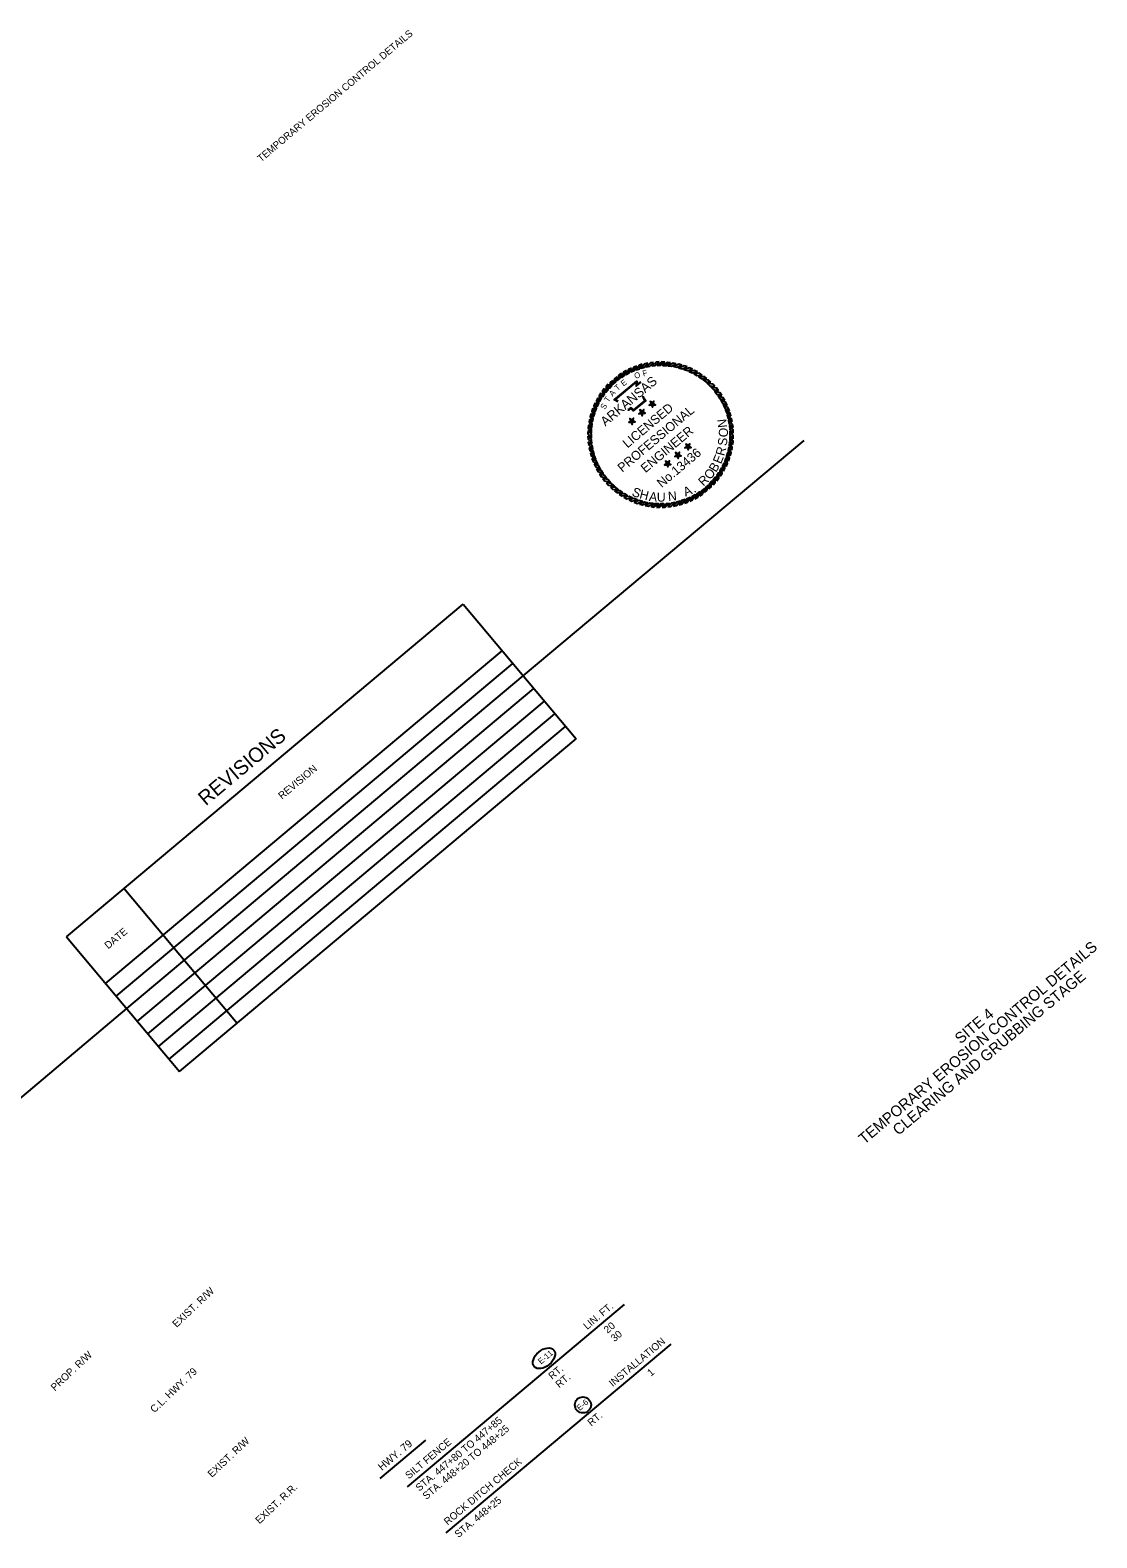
# Model space of a CAD drawing. Extents: x 1430270 to 1431940, y 1964864 to 1966264.
# Drawn here: x 1431064 to 1431940, y 1965025 to 1966264 of the extents above; entities that cross this region are included whole.
import ezdxf

# ---------------------------------------------------------------- set-up
doc = ezdxf.new("R2010")
doc.units = 0
for name, color, linetype in [('1', 7, 'Continuous'), ('44', 7, 'Continuous'), ('60', 7, 'Continuous'), ('Default', 7, 'Continuous'), ('G-ANNO-SYMB', 7, 'Continuous'), ('R_Draft', 7, 'Continuous')]:
    doc.layers.add(name, color=color, linetype=linetype)

msp = doc.modelspace()

# ---------------------------------------------------------------- linework, layer by layer
at = {"layer": '1'}
for p, q in [((1431469.3, 1965733.3), (1431699.9, 1965926.7)), ((1430924.6, 1965276.1), (1431143.8, 1965460.1))]:
    msp.add_line(p, q, dxfattribs=at)
msp.add_circle((1431518.4, 1965134.6), 6.61, dxfattribs=at)
msp.add_ellipse((1431486.4, 1965172.9), major_axis=(8.06, 6.76), ratio=0.638788, dxfattribs=at)
at = {"layer": '44'}
for p, q in [((1431374.3, 1965067.4), (1431552.6, 1965217.1)), ((1431406.1, 1965029.6), (1431590.7, 1965184.5)), ((1431352, 1965074.3), (1431389.4, 1965105.7))]:
    msp.add_line(p, q, dxfattribs=at)
at = {"layer": 'Default'}
for p, q in [((1431094.3, 1965519.1), (1431419.9, 1965792.3)), ((1431419.9, 1965792.3), (1431512.7, 1965681.6)), ((1431126.4, 1965480.8), (1431452, 1965754)), ((1431135.1, 1965470.4), (1431460.7, 1965743.6)), ((1431143.8, 1965460.1), (1431469.3, 1965733.3)), ((1431152.5, 1965449.7), (1431478, 1965722.9)), ((1431152.5, 1965449.7), (1431478, 1965722.9)), ((1431161.1, 1965439.4), (1431486.7, 1965712.6)), ((1431169.8, 1965429.1), (1431495.4, 1965702.2)), ((1431178.5, 1965418.7), (1431504.1, 1965691.9)), ((1431187.2, 1965408.4), (1431512.7, 1965681.6)), ((1431141.6, 1965558.8), (1431234.5, 1965448.1)), ((1431094.3, 1965519.1), (1431187.2, 1965408.4))]:
    msp.add_line(p, q, dxfattribs=at)
at = {"layer": 'G-ANNO-SYMB'}
for points in [[(1431567.1, 1965989.3), (1431564.7, 1965988.6), (1431562.1, 1965984.8), (1431564.7, 1965985.7)], [(1431571.7, 1965990.3), (1431569.2, 1965989.8), (1431566.3, 1965986.2), (1431569, 1965986.9)], [(1431576.3, 1965990.9), (1431573.8, 1965990.6), (1431570.6, 1965987.3), (1431573.4, 1965987.8)], [(1431581, 1965991.2), (1431578.4, 1965991.1), (1431575.1, 1965988), (1431577.8, 1965988.3)], [(1431585.7, 1965991.1), (1431583.1, 1965991.2), (1431579.5, 1965988.4), (1431582.3, 1965988.5)], [(1431590.4, 1965990.6), (1431587.8, 1965990.9), (1431584, 1965988.4), (1431586.7, 1965988.3)], [(1431595, 1965989.8), (1431592.5, 1965990.3), (1431588.4, 1965988.1), (1431591.2, 1965987.8)], [(1431599.5, 1965988.6), (1431597, 1965989.3), (1431592.9, 1965987.5), (1431595.6, 1965986.9)], [(1431542.6, 1965976.1), (1431540.7, 1965974.4), (1431540.1, 1965969.8), (1431542, 1965971.9)], [(1431546.2, 1965979.1), (1431544.2, 1965977.5), (1431543.2, 1965973), (1431545.3, 1965974.9)], [(1431550, 1965981.8), (1431547.9, 1965980.3), (1431546.6, 1965976), (1431548.8, 1965977.6)], [(1431554.1, 1965984.1), (1431551.8, 1965982.9), (1431550.2, 1965978.6), (1431552.5, 1965980.1)], [(1431558.3, 1965986.2), (1431555.9, 1965985.1), (1431554, 1965981), (1431556.4, 1965982.3)], [(1431562.6, 1965987.9), (1431560.2, 1965987), (1431557.9, 1965983), (1431560.5, 1965984.2)], [(1431603.9, 1965987.1), (1431601.5, 1965988), (1431597.2, 1965986.5), (1431599.9, 1965985.7)], [(1431608.2, 1965985.2), (1431605.9, 1965986.3), (1431601.5, 1965985.1), (1431604.1, 1965984.1)], [(1431612.4, 1965983), (1431610.1, 1965984.3), (1431605.6, 1965983.4), (1431608.1, 1965982.2)], [(1431616.3, 1965980.5), (1431614.2, 1965981.9), (1431609.6, 1965981.4), (1431612, 1965980)], [(1431620, 1965977.7), (1431618, 1965979.2), (1431613.4, 1965979.1), (1431615.7, 1965977.6)], [(1431623.5, 1965974.6), (1431621.6, 1965976.3), (1431617.1, 1965976.5), (1431619.2, 1965974.8)], [(1431533.2, 1965965.6), (1431531.8, 1965963.5), (1431532.3, 1965959), (1431533.7, 1965961.4)], [(1431536.1, 1965969.4), (1431534.5, 1965967.4), (1431534.6, 1965962.8), (1431536.2, 1965965.1)], [(1431539.2, 1965972.9), (1431537.4, 1965971), (1431537.2, 1965966.4), (1431539, 1965968.6)], [(1431626.8, 1965971.2), (1431625, 1965973.1), (1431620.5, 1965973.7), (1431622.5, 1965971.7)], [(1431629.8, 1965967.6), (1431628.2, 1965969.6), (1431623.7, 1965970.5), (1431625.5, 1965968.5)], [(1431632.4, 1965963.7), (1431631, 1965965.8), (1431626.6, 1965967.1), (1431628.3, 1965964.9)], [(1431634.8, 1965959.7), (1431633.5, 1965961.9), (1431629.3, 1965963.5), (1431630.8, 1965961.2)], [(1431526.6, 1965953.3), (1431525.8, 1965950.9), (1431527.3, 1965946.6), (1431528.1, 1965949.2)], [(1431528.5, 1965957.6), (1431527.4, 1965955.2), (1431528.6, 1965950.8), (1431529.6, 1965953.4)], [(1431530.7, 1965961.7), (1431529.5, 1965959.5), (1431530.3, 1965955), (1431531.5, 1965957.5)], [(1431566.9, 1965949.7), (1431566.9, 1965950.8), (1431565.2, 1965951.8), (1431565.9, 1965950)], [(1431566.9, 1965949.7), (1431567.9, 1965950.1), (1431568.4, 1965952.1), (1431566.9, 1965950.8)], [(1431575.3, 1965956.8), (1431574.3, 1965957), (1431572.8, 1965955.7), (1431574.7, 1965955.9)], [(1431575.3, 1965956.8), (1431575.2, 1965957.8), (1431573.5, 1965958.8), (1431574.3, 1965957)], [(1431575.3, 1965956.8), (1431574.7, 1965955.9), (1431575.5, 1965954), (1431576, 1965956)], [(1431575.3, 1965956.8), (1431576.2, 1965957.1), (1431576.7, 1965959.1), (1431575.2, 1965957.8)], [(1431575.3, 1965956.8), (1431576, 1965956), (1431577.9, 1965956.1), (1431576.2, 1965957.1)], [(1431636.9, 1965955.5), (1431635.8, 1965957.8), (1431631.6, 1965959.8), (1431633, 1965957.3)], [(1431638.6, 1965951.1), (1431637.7, 1965953.5), (1431633.7, 1965955.8), (1431634.8, 1965953.3)], [(1431639.9, 1965946.6), (1431639.2, 1965949.1), (1431635.4, 1965951.7), (1431636.4, 1965949.1)], [(1431523.1, 1965939.7), (1431522.8, 1965937.2), (1431525.3, 1965933.3), (1431525.4, 1965936.1)], [(1431523.9, 1965944.3), (1431523.4, 1965941.8), (1431525.6, 1965937.8), (1431526, 1965940.5)], [(1431525.1, 1965948.8), (1431524.4, 1965946.4), (1431526.3, 1965942.2), (1431526.9, 1965944.9)], [(1431558.6, 1965942.7), (1431557.6, 1965943), (1431556, 1965941.7), (1431558, 1965941.8)], [(1431558.6, 1965942.7), (1431558.5, 1965943.8), (1431556.8, 1965944.8), (1431557.6, 1965943)], [(1431558.6, 1965942.7), (1431558, 1965941.8), (1431558.8, 1965940), (1431559.2, 1965941.9)], [(1431558.6, 1965942.7), (1431559.5, 1965943.1), (1431560, 1965945), (1431558.5, 1965943.8)], [(1431558.6, 1965942.7), (1431559.2, 1965941.9), (1431561.2, 1965942.1), (1431559.5, 1965943.1)], [(1431566.9, 1965949.7), (1431565.9, 1965950), (1431564.4, 1965948.7), (1431566.4, 1965948.9)], [(1431566.9, 1965949.7), (1431566.4, 1965948.9), (1431567.1, 1965947), (1431567.6, 1965948.9)], [(1431566.9, 1965949.7), (1431567.6, 1965948.9), (1431569.6, 1965949.1), (1431567.9, 1965950.1)], [(1431640.9, 1965942), (1431640.4, 1965944.6), (1431636.9, 1965947.4), (1431637.6, 1965944.8)], [(1431641.6, 1965937.4), (1431641.3, 1965939.9), (1431637.9, 1965943.1), (1431638.4, 1965940.4)], [(1431522.6, 1965935), (1431522.5, 1965932.5), (1431525.3, 1965928.8), (1431525.3, 1965931.6)], [(1431522.5, 1965930.4), (1431522.7, 1965927.8), (1431525.7, 1965924.4), (1431525.4, 1965927.2)], [(1431641.8, 1965932.7), (1431641.7, 1965935.3), (1431638.7, 1965938.7), (1431639, 1965935.9)], [(1431641.3, 1965923.4), (1431641.6, 1965925.9), (1431639.1, 1965929.8), (1431638.9, 1965927)], [(1431641.8, 1965928), (1431641.8, 1965930.6), (1431639.1, 1965934.2), (1431639.1, 1965931.5)], [(1431522.8, 1965925.7), (1431523.1, 1965923.1), (1431526.4, 1965920), (1431526, 1965922.7)], [(1431523.5, 1965921), (1431524, 1965918.5), (1431527.5, 1965915.6), (1431526.8, 1965918.3)], [(1431524.5, 1965916.5), (1431525.2, 1965914), (1431528.9, 1965911.4), (1431528, 1965914)], [(1431596.3, 1965914.7), (1431595.3, 1965915), (1431593.8, 1965913.7), (1431595.7, 1965913.9)], [(1431596.3, 1965914.7), (1431596.2, 1965915.8), (1431594.5, 1965916.8), (1431595.3, 1965915)], [(1431596.3, 1965914.7), (1431595.7, 1965913.9), (1431596.5, 1965912), (1431597, 1965913.9)], [(1431596.3, 1965914.7), (1431597.3, 1965915.1), (1431597.7, 1965917.1), (1431596.2, 1965915.8)], [(1431596.3, 1965914.7), (1431597, 1965913.9), (1431598.9, 1965914.1), (1431597.3, 1965915.1)], [(1431604.6, 1965921.8), (1431603.6, 1965922), (1431602.1, 1965920.7), (1431604.1, 1965920.9)], [(1431604.6, 1965921.8), (1431604.6, 1965922.8), (1431602.9, 1965923.8), (1431603.6, 1965922)], [(1431604.6, 1965921.8), (1431604.1, 1965920.9), (1431604.8, 1965919), (1431605.3, 1965921)], [(1431604.6, 1965921.8), (1431605.6, 1965922.1), (1431606.1, 1965924.1), (1431604.6, 1965922.8)], [(1431604.6, 1965921.8), (1431605.3, 1965921), (1431607.3, 1965921.1), (1431605.6, 1965922.1)], [(1431637.8, 1965909.8), (1431638.6, 1965912.2), (1431637.1, 1965916.5), (1431636.3, 1965913.9)], [(1431639.3, 1965914.2), (1431640, 1965916.7), (1431638.1, 1965920.9), (1431637.5, 1965918.2)], [(1431640.5, 1965918.8), (1431641, 1965921.3), (1431638.8, 1965925.3), (1431638.4, 1965922.6)], [(1431525.8, 1965912), (1431526.7, 1965909.6), (1431530.7, 1965907.3), (1431529.6, 1965909.8)], [(1431527.5, 1965907.6), (1431528.6, 1965905.3), (1431532.7, 1965903.3), (1431531.4, 1965905.8)], [(1431529.6, 1965903.4), (1431530.8, 1965901.2), (1431535.1, 1965899.5), (1431533.6, 1965901.9)], [(1431587.9, 1965907.7), (1431586.9, 1965908), (1431585.4, 1965906.7), (1431587.4, 1965906.8)], [(1431587.9, 1965907.7), (1431587.9, 1965908.8), (1431586.2, 1965909.8), (1431586.9, 1965908)], [(1431587.9, 1965907.7), (1431587.4, 1965906.8), (1431588.1, 1965905), (1431588.6, 1965906.9)], [(1431587.9, 1965907.7), (1431588.9, 1965908.1), (1431589.4, 1965910), (1431587.9, 1965908.8)], [(1431587.9, 1965907.7), (1431588.6, 1965906.9), (1431590.6, 1965907.1), (1431588.9, 1965908.1)], [(1431631.1, 1965897.4), (1431632.6, 1965899.6), (1431632.1, 1965904.1), (1431630.7, 1965901.7)], [(1431633.7, 1965901.4), (1431634.9, 1965903.6), (1431634.1, 1965908.1), (1431632.9, 1965905.6)], [(1431635.9, 1965905.5), (1431637, 1965907.8), (1431635.8, 1965912.3), (1431634.8, 1965909.7)], [(1431532, 1965899.4), (1431533.4, 1965897.2), (1431537.8, 1965895.9), (1431536.1, 1965898.1)], [(1431534.6, 1965895.5), (1431536.2, 1965893.5), (1431540.7, 1965892.6), (1431538.9, 1965894.6)], [(1431537.6, 1965891.9), (1431539.4, 1965890), (1431543.9, 1965889.4), (1431541.9, 1965891.3)], [(1431618.2, 1965884), (1431620.2, 1965885.6), (1431621.2, 1965890), (1431619.1, 1965888.2)], [(1431621.8, 1965887), (1431623.7, 1965888.7), (1431624.3, 1965893.2), (1431622.4, 1965891.2)], [(1431625.2, 1965890.2), (1431626.9, 1965892.1), (1431627.2, 1965896.7), (1431625.4, 1965894.5)], [(1431628.3, 1965893.7), (1431629.9, 1965895.7), (1431629.8, 1965900.3), (1431628.2, 1965898)], [(1431540.9, 1965888.5), (1431542.7, 1965886.8), (1431547.3, 1965886.5), (1431545.2, 1965888.3)], [(1431544.4, 1965885.4), (1431546.4, 1965883.8), (1431550.9, 1965883.9), (1431548.7, 1965885.5)], [(1431548.1, 1965882.6), (1431550.2, 1965881.2), (1431554.8, 1965881.6), (1431552.4, 1965883)], [(1431552, 1965880.1), (1431554.3, 1965878.8), (1431558.8, 1965879.6), (1431556.3, 1965880.8)], [(1431556.2, 1965877.9), (1431558.5, 1965876.8), (1431562.9, 1965878), (1431560.3, 1965879)], [(1431560.5, 1965876), (1431562.9, 1965875.1), (1431567.2, 1965876.6), (1431564.5, 1965877.4)], [(1431592.7, 1965872.8), (1431595.2, 1965873.3), (1431598.1, 1965876.9), (1431595.4, 1965876.2)], [(1431597.3, 1965873.8), (1431599.7, 1965874.5), (1431602.3, 1965878.3), (1431599.7, 1965877.4)], [(1431601.8, 1965875.2), (1431604.2, 1965876.1), (1431606.4, 1965880), (1431603.9, 1965878.9)], [(1431606.1, 1965876.9), (1431608.4, 1965878), (1431610.4, 1965882.1), (1431608, 1965880.8)], [(1431610.3, 1965878.9), (1431612.6, 1965880.2), (1431614.2, 1965884.5), (1431611.9, 1965883)], [(1431614.4, 1965881.3), (1431616.5, 1965882.7), (1431617.8, 1965887.1), (1431615.6, 1965885.4)], [(1431564.9, 1965874.4), (1431567.4, 1965873.8), (1431571.5, 1965875.6), (1431568.8, 1965876.2)], [(1431569.4, 1965873.3), (1431571.9, 1965872.8), (1431576, 1965875), (1431573.2, 1965875.3)], [(1431574, 1965872.4), (1431576.6, 1965872.1), (1431580.4, 1965874.6), (1431577.7, 1965874.8)], [(1431578.7, 1965872), (1431581.3, 1965871.9), (1431584.9, 1965874.7), (1431582.1, 1965874.6)], [(1431583.4, 1965871.9), (1431585.9, 1965872), (1431589.3, 1965875.1), (1431586.6, 1965874.8)], [(1431588.1, 1965872.2), (1431590.6, 1965872.5), (1431593.8, 1965875.8), (1431591, 1965875.3)]]:
    msp.add_lwpolyline(points, close=True, dxfattribs=at)
for points in [[(1431547, 1965958.6), (1431544, 1965960), (1431562.5, 1965975.5), (1431562.5, 1965972.2), (1431563.8, 1965973.3), (1431564.8, 1965974.2), (1431566, 1965975)], [(1431547.2, 1965958.9), (1431544.7, 1965960.1), (1431562.1, 1965974.7), (1431562.2, 1965971.4), (1431564, 1965973), (1431565.1, 1965973.9), (1431566.2, 1965974.6)], [(1431568, 1965963), (1431567.9, 1965962.5), (1431568.1, 1965962), (1431568.8, 1965960.9), (1431569.9, 1965959.7), (1431559.6, 1965951), (1431558.1, 1965952.8), (1431557.8, 1965953.1), (1431557.3, 1965952.9), (1431555.8, 1965951.7), (1431555.2, 1965951.9)], [(1431567.6, 1965963), (1431567.5, 1965962.4), (1431567.8, 1965961.8), (1431568.5, 1965960.7), (1431569.3, 1965959.7), (1431559.6, 1965951.6), (1431558.4, 1965953), (1431557.9, 1965953.6), (1431557.1, 1965953.2), (1431555.7, 1965952.1), (1431555.3, 1965952.2)]]:
    msp.add_lwpolyline(points, dxfattribs=at)

# ---------------------------------------------------------------- texts
at = {"layer": '1'}
for s, height, p in [('TEMPORARY EROSION CONTROL DETAILS', 5.862, (1431254.1, 1966155.1)), ('E-11', 4.8, (1431483.9, 1965167.7)), ('E-6 ', 4.8, (1431515.7, 1965129.6))]:
    msp.add_text(s, height=height, rotation=40, dxfattribs=at).set_placement(p)
at = {"layer": '44'}
for s, height, p in [('LIN. FT.', 6, (1431521.8, 1965196.1)), ('20', 6, (1431538.6, 1965193)), ('30', 6, (1431544.3, 1965186.1)), ('INSTALLATION', 6, (1431542.8, 1965149.2)), ('RT.', 6, (1431493.1, 1965155.1)), ('RT.', 6, (1431498.9, 1965148.2)), ('1', 6, (1431574.2, 1965157.7)), ('STA. 447+80 TO 447+85', 6, (1431384, 1965063.3)), ('RT.', 6, (1431525.2, 1965116.8)), ('STA. 448+20 TO 448+25', 6, (1431389.8, 1965056.5)), ('HWY. 79', 6.25, (1431353.3, 1965080.3)), ('SILT FENCE      ', 6, (1431375.5, 1965073.4)), ('ROCK DITCH CHECK', 6, (1431407.3, 1965035.5)), ('STA. 448+25', 6, (1431416.1, 1965025.1))]:
    msp.add_text(s, height=height, rotation=40, dxfattribs=at).set_placement(p)
at = {"layer": '60'}
for s, p in [('TEMPORARY EROSION CONTROL DETAILS', (1431749.4, 1965348.2)), ('CLEARING AND GRUBBING STAGE', (1431777.4, 1965355.5)), ('SITE 4', (1431828.4, 1965430.6))]:
    msp.add_text(s, height=9, rotation=40, dxfattribs=at).set_placement(p)
at = {"layer": 'Default'}
for s, height, p in [('REVISIONS', 12, (1431208.7, 1965626.2)), ('REVISION', 6, (1431271.3, 1965631.7)), ('DATE', 6, (1431128.6, 1965508.7))]:
    msp.add_text(s, height=height, rotation=40, dxfattribs=at).set_placement(p)
at = {"layer": 'G-ANNO-SYMB'}
for s, height, rotation, p in [('ARKANSAS', 7.75, 40, (1431536.8, 1965938)), ('E', 4.75, 36.672, (1431551.6, 1965971)), ('O', 4.75, 21.2218, (1431561.5, 1965977.2)), ('F', 4.75, 15.3628, (1431568, 1965979.3)), ('A', 4.75, 48.6788, (1431542.8, 1965962.5)), ('T', 4.75, 41.4789, (1431546.8, 1965967.2)), ('S', 4.75, 59.7726, (1431536.4, 1965951.7)), ('T', 4.75, 56.9015, (1431539.3, 1965957.7)), ('PROFESSIONAL', 7.5, 40, (1431550.7, 1965900.2)), ('LICENSED', 7.5, 40, (1431554.9, 1965920.1)), ('N', 7.5, 96.1007, (1431636.8, 1965937.6)), ('ENGINEER', 7.5, 40, (1431569.7, 1965899.8)), ('S', 7.5, 83.4878, (1431636.4, 1965922)), ('O', 7.5, 84.7757, (1431637.1, 1965929.1)), ('No.13436', 7.47, 40, (1431583, 1965887.6)), ('E', 7.5, 67.8315, (1431631.7, 1965907)), ('R', 7.5, 75.6597, (1431634.4, 1965913.6)), ('O', 7.5, 51.4296, (1431622.9, 1965894)), ('B', 7.5, 58.885, (1431627.6, 1965900.1)), ('R', 7.5, 43.2287, (1431617.3, 1965888.7)), ('S', 7.5, 338.1636, (1431557.9, 1965881.7)), ('H', 7.5, 345.619, (1431564.3, 1965879.3)), ('A', 7.5, 353.4472, (1431572.3, 1965877.2)), ('U', 7.5, 0.9026, (1431579.1, 1965876.4)), ('N', 7.5, 4.9326, (1431588.5, 1965877)), ('A', 7.5, 23.0991, (1431602.6, 1965880.5)), ('.', 7.5, 31.3, (1431609.7, 1965883.5))]:
    msp.add_text(s, height=height, rotation=rotation, dxfattribs=at).set_placement(p)
at = {"layer": 'R_Draft'}
for s, rotation, p in [('EXIST. R/W', 43.366, (1431184.7, 1965197.8)), ('PROP. R/W', 43.366, (1431084.8, 1965145.7)), ('C.L. HWY. 79', 43.4244, (1431166.5, 1965127.7)), ('EXIST. R/W', 43.366, (1431213.7, 1965074.6)), ('EXIST. R.R.', 43.3919, (1431252.8, 1965036.5))]:
    msp.add_text(s, height=6, rotation=rotation, dxfattribs=at).set_placement(p)

doc.saveas('drawing.dxf')
